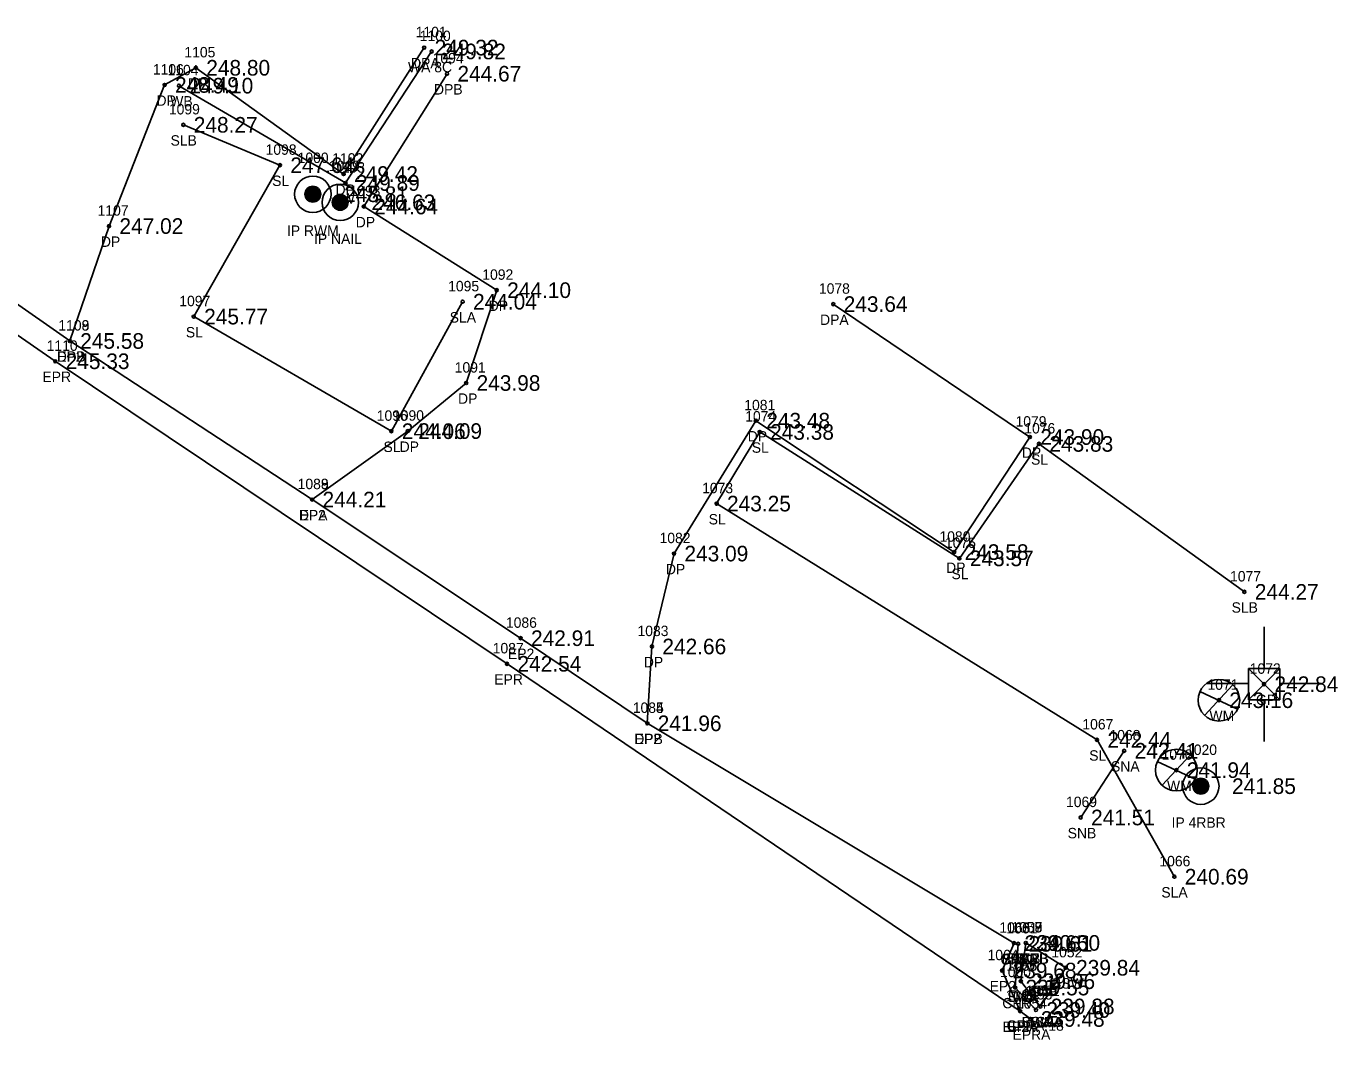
# Model space of a CAD drawing. Extents: x 1961231 to 1962574, y 799865 to 801120.
# Drawn here: x 1962180.3 to 1962306.3, y 800364.5 to 800461.9 of the extents above; entities that cross this region are included whole.
import ezdxf

# ---------------------------------------------------------------- set-up
doc = ezdxf.new("R2010")
doc.units = 0
for name, color, linetype in [('RD_EX_BldgApp', 7, 'Continuous'), ('RD_EX_BldgApp_txCode', 7, 'Continuous'), ('RD_EX_Conc', 7, 'Continuous'), ('RD_EX_Conc_txCode', 7, 'Continuous'), ('RD_EX_Driveway', 7, 'Continuous'), ('RD_EX_Driveway_txCode', 7, 'Continuous'), ('RD_EX_DV_Prop_txCode', 7, 'Continuous'), ('RD_EX_DV_PropPin', 7, 'Continuous'), ('RD_EX_Misc_txCode', 7, 'Continuous'), ('RD_EX_Road', 7, 'Continuous'), ('RD_EX_Road_txCode', 7, 'Continuous'), ('RD_EX_TX_BldgApp_ELEV', 7, 'Continuous'), ('RD_EX_TX_Conc_ELEV', 7, 'Continuous'), ('RD_EX_TX_Driveway_ELEV', 7, 'Continuous'), ('RD_EX_TX_DV_Prop_ELEV', 7, 'Continuous'), ('RD_EX_TX_Misc_ELEV', 7, 'Continuous'), ('RD_EX_TX_Road_ELEV', 7, 'Continuous'), ('RD_EX_TX_UT_ELEV', 7, 'Continuous'), ('RD_EX_TX_VEG_ELEV', 7, 'Continuous'), ('RD_EX_UT', 7, 'Continuous'), ('RD_EX_UT_txCode', 7, 'Continuous'), ('RD_EX_VEG', 7, 'Continuous'), ('RD_EX_VEG_txCode', 7, 'Continuous'), ('RD_SMD_Locator', 7, 'Continuous')]:
    doc.layers.add(name, color=color, linetype=linetype)

msp = doc.modelspace()

# ---------------------------------------------------------------- linework, layer by layer
at = {"layer": 'RD_EX_BldgApp'}
msp.add_line((1962285.75, 800392.3), (1962281.57, 800385.89), dxfattribs=at)
msp.add_lwpolyline([(1962219.21, 800459.5), (1962210.94, 800446.86), (1962194.94, 800456.21)], dxfattribs=at)
at = {"layer": 'RD_EX_Conc'}
for points in [[(1962277.69, 800367.73), (1962275.82, 800370.16), (1962276.3, 800373.84)], [(1962277.69, 800367.73), (1962280.13, 800371.45), (1962276.3, 800373.84)], [(1962277.27, 800367.4), (1962275.27, 800369.55), (1962275.56, 800373.75)]]:
    msp.add_lwpolyline(points, dxfattribs=at)
at = {"layer": 'RD_EX_Driveway'}
for points in [[(1962218.5, 800459.87), (1962210.76, 800447.72), (1962196.56, 800457.93), (1962193.56, 800456.28), (1962188.22, 800442.72), (1962184.45, 800431.68)], [(1962207.73, 800416.44), (1962216.92, 800423.02), (1962222.53, 800427.64), (1962225.47, 800436.56), (1962212.7, 800444.6), (1962220.69, 800457.36)], [(1962257.8, 800435.22), (1962276.69, 800422.45), (1962269.42, 800411.39), (1962250.36, 800424.02), (1962242.5, 800411.25), (1962240.38, 800402.32), (1962239.93, 800394.94)]]:
    msp.add_lwpolyline(points, dxfattribs=at)
at = {"layer": 'RD_EX_DV_PropPin'}
for p, q in [((1962207.07, 800445.59), (1962207.07, 800445.98)), ((1962207.1, 800445.48), (1962207.1, 800446.08)), ((1962207.14, 800445.41), (1962207.14, 800446.15)), ((1962207.17, 800445.36), (1962207.17, 800446.21)), ((1962207.21, 800445.31), (1962207.21, 800446.26)), ((1962207.24, 800445.27), (1962207.24, 800446.3)), ((1962207.28, 800445.23), (1962207.28, 800446.33)), ((1962207.31, 800445.2), (1962207.31, 800446.36)), ((1962207.35, 800445.17), (1962207.35, 800446.39)), ((1962207.38, 800445.15), (1962207.38, 800446.42)), ((1962207.42, 800445.13), (1962207.42, 800446.44)), ((1962207.45, 800445.11), (1962207.45, 800446.46)), ((1962207.49, 800445.09), (1962207.49, 800446.48)), ((1962207.52, 800445.07), (1962207.52, 800446.49)), ((1962207.56, 800445.06), (1962207.56, 800446.5)), ((1962207.59, 800445.05), (1962207.59, 800446.51)), ((1962207.63, 800445.04), (1962207.63, 800446.52)), ((1962207.66, 800445.03), (1962207.66, 800446.53)), ((1962207.7, 800445.03), (1962207.7, 800446.54)), ((1962207.73, 800445.02), (1962207.73, 800446.54)), ((1962207.77, 800445.02), (1962207.77, 800446.54)), ((1962207.8, 800445.02), (1962207.8, 800446.54)), ((1962207.84, 800445.02), (1962207.84, 800446.54)), ((1962207.87, 800445.02), (1962207.87, 800446.54)), ((1962207.91, 800445.03), (1962207.91, 800446.54)), ((1962207.94, 800445.03), (1962207.94, 800446.53)), ((1962207.98, 800445.04), (1962207.98, 800446.52)), ((1962208.01, 800445.05), (1962208.01, 800446.51)), ((1962208.05, 800445.06), (1962208.05, 800446.5)), ((1962208.08, 800445.07), (1962208.08, 800446.49)), ((1962208.12, 800445.09), (1962208.12, 800446.48)), ((1962208.15, 800445.11), (1962208.15, 800446.46)), ((1962208.19, 800445.13), (1962208.19, 800446.44)), ((1962208.22, 800445.15), (1962208.22, 800446.42)), ((1962208.26, 800445.17), (1962208.26, 800446.39)), ((1962208.29, 800445.2), (1962208.29, 800446.36)), ((1962208.33, 800445.23), (1962208.33, 800446.33)), ((1962208.36, 800445.27), (1962208.36, 800446.3)), ((1962208.4, 800445.31), (1962208.4, 800446.26)), ((1962208.43, 800445.36), (1962208.43, 800446.21)), ((1962208.47, 800445.41), (1962208.47, 800446.15)), ((1962208.5, 800445.48), (1962208.5, 800446.08)), ((1962208.54, 800445.59), (1962208.54, 800445.98)), ((1962209.98, 800444.39), (1962209.98, 800445.61)), ((1962210.01, 800444.36), (1962210.01, 800445.63)), ((1962210.05, 800444.34), (1962210.05, 800445.65)), ((1962210.08, 800444.32), (1962210.08, 800445.67)), ((1962210.12, 800444.3), (1962210.12, 800445.69)), ((1962210.15, 800444.29), (1962210.15, 800445.7)), ((1962210.19, 800444.28), (1962210.19, 800445.72)), ((1962210.22, 800444.27), (1962210.22, 800445.73)), ((1962210.26, 800444.26), (1962210.26, 800445.74)), ((1962210.29, 800444.25), (1962210.29, 800445.75)), ((1962210.33, 800444.24), (1962210.33, 800445.75)), ((1962210.36, 800444.24), (1962210.36, 800445.75)), ((1962210.4, 800444.24), (1962210.4, 800445.76)), ((1962210.43, 800444.24), (1962210.43, 800445.76)), ((1962210.47, 800444.24), (1962210.47, 800445.76)), ((1962210.5, 800444.24), (1962210.5, 800445.75)), ((1962210.54, 800444.24), (1962210.54, 800445.75)), ((1962210.57, 800444.25), (1962210.57, 800445.75)), ((1962210.61, 800444.26), (1962210.61, 800445.74)), ((1962210.64, 800444.27), (1962210.64, 800445.73)), ((1962210.68, 800444.28), (1962210.68, 800445.72)), ((1962210.71, 800444.29), (1962210.71, 800445.7)), ((1962210.75, 800444.3), (1962210.75, 800445.69)), ((1962210.78, 800444.32), (1962210.78, 800445.67)), ((1962210.82, 800444.34), (1962210.82, 800445.65)), ((1962210.85, 800444.36), (1962210.85, 800445.63)), ((1962210.89, 800444.39), (1962210.89, 800445.61)), ((1962209.7, 800444.8), (1962209.7, 800445.19)), ((1962209.73, 800444.7), (1962209.73, 800445.3)), ((1962209.77, 800444.63), (1962209.77, 800445.37)), ((1962209.8, 800444.57), (1962209.8, 800445.42)), ((1962209.84, 800444.52), (1962209.84, 800445.47)), ((1962209.87, 800444.48), (1962209.87, 800445.51)), ((1962209.91, 800444.45), (1962209.91, 800445.55)), ((1962209.94, 800444.42), (1962209.94, 800445.58)), ((1962210.92, 800444.42), (1962210.92, 800445.58)), ((1962210.96, 800444.45), (1962210.96, 800445.55)), ((1962210.99, 800444.48), (1962210.99, 800445.51)), ((1962211.03, 800444.52), (1962211.03, 800445.47)), ((1962211.06, 800444.57), (1962211.06, 800445.42)), ((1962211.1, 800444.63), (1962211.1, 800445.37)), ((1962211.13, 800444.7), (1962211.13, 800445.3)), ((1962211.17, 800444.8), (1962211.17, 800445.19)), ((1962292.38, 800388.71), (1962292.38, 800389.1)), ((1962292.41, 800388.61), (1962292.41, 800389.2)), ((1962292.45, 800388.53), (1962292.45, 800389.27)), ((1962292.48, 800388.48), (1962292.48, 800389.33)), ((1962292.52, 800388.43), (1962292.52, 800389.38)), ((1962292.55, 800388.39), (1962292.55, 800389.42)), ((1962292.59, 800388.35), (1962292.59, 800389.45)), ((1962292.62, 800388.32), (1962292.62, 800389.49)), ((1962292.66, 800388.29), (1962292.66, 800389.51)), ((1962292.69, 800388.27), (1962292.69, 800389.54)), ((1962292.73, 800388.25), (1962292.73, 800389.56)), ((1962292.76, 800388.23), (1962292.76, 800389.58)), ((1962292.8, 800388.21), (1962292.8, 800389.6)), ((1962292.83, 800388.2), (1962292.83, 800389.61)), ((1962292.87, 800388.18), (1962292.87, 800389.62)), ((1962292.9, 800388.17), (1962292.9, 800389.64)), ((1962292.94, 800388.16), (1962292.94, 800389.64)), ((1962292.97, 800388.16), (1962292.97, 800389.65)), ((1962293.01, 800388.15), (1962293.01, 800389.66)), ((1962293.04, 800388.15), (1962293.04, 800389.66)), ((1962293.08, 800388.14), (1962293.08, 800389.66)), ((1962293.11, 800388.14), (1962293.11, 800389.67)), ((1962293.15, 800388.14), (1962293.15, 800389.66)), ((1962293.18, 800388.15), (1962293.18, 800389.66)), ((1962293.22, 800388.15), (1962293.22, 800389.66)), ((1962293.25, 800388.16), (1962293.25, 800389.65)), ((1962293.29, 800388.16), (1962293.29, 800389.64)), ((1962293.32, 800388.17), (1962293.32, 800389.64)), ((1962293.36, 800388.18), (1962293.36, 800389.62)), ((1962293.39, 800388.2), (1962293.39, 800389.61)), ((1962293.43, 800388.21), (1962293.43, 800389.6)), ((1962293.46, 800388.23), (1962293.46, 800389.58)), ((1962293.5, 800388.25), (1962293.5, 800389.56)), ((1962293.53, 800388.27), (1962293.53, 800389.54)), ((1962293.57, 800388.29), (1962293.57, 800389.51)), ((1962293.6, 800388.32), (1962293.6, 800389.49)), ((1962293.64, 800388.35), (1962293.64, 800389.45)), ((1962293.67, 800388.39), (1962293.67, 800389.42)), ((1962293.71, 800388.43), (1962293.71, 800389.38)), ((1962293.74, 800388.48), (1962293.74, 800389.33)), ((1962293.78, 800388.53), (1962293.78, 800389.27)), ((1962293.81, 800388.61), (1962293.81, 800389.2)), ((1962293.85, 800388.71), (1962293.85, 800389.1))]:
    msp.add_line(p, q, dxfattribs=at)
for centre, radius in [((1962207.8, 800445.78), 1.75), ((1962207.8, 800445.78), 0.761), ((1962210.43, 800445), 1.75), ((1962210.43, 800445), 0.761), ((1962293.11, 800388.9), 1.75), ((1962293.11, 800388.9), 0.761)]:
    msp.add_circle(centre, radius, dxfattribs=at)
at = {"layer": 'RD_EX_Road'}
for points in [[(1962276.74, 800366.53), (1962275.76, 800367.28), (1962226.46, 800400.66), (1962183.05, 800429.73), (1962145.98, 800455.38), (1962104.4, 800484.06), (1962056.77, 800517.94), (1962023.95, 800541.05), (1961991.87, 800563.56), (1961983.89, 800569.94), (1961938.77, 800603.67), (1961913.43, 800623.83), (1961897.73, 800636.17), (1961851.62, 800671.61), (1961815.86, 800699.48), (1961795.77, 800715.49), (1961771.88, 800733.73), (1961750.77, 800750.96), (1961735.63, 800762.82), (1961702.92, 800788.52)], [(1962275.76, 800367.28), (1962274.03, 800371.18), (1962275.17, 800373.82), (1962239.93, 800394.94), (1962227.76, 800403.12), (1962207.73, 800416.44), (1962184.45, 800431.68), (1962152.89, 800453.77), (1962107.43, 800485.96), (1962091.52, 800497.24), (1962058.28, 800520.2), (1962027.14, 800543.26), (1961995.14, 800564.69), (1961983.89, 800569.94)]]:
    msp.add_lwpolyline(points, dxfattribs=at)
at = {"layer": 'RD_EX_UT'}
for p, q in [((1962299.19, 800400.2), (1962299.19, 800404.2)), ((1962300.69, 800400.2), (1962297.69, 800397.2)), ((1962297.69, 800400.2), (1962300.69, 800397.2)), ((1962300.69, 800400.2), (1962297.69, 800400.2)), ((1962297.69, 800400.2), (1962297.69, 800397.2)), ((1962300.69, 800397.2), (1962300.69, 800400.2)), ((1962293.02, 800398), (1962296.65, 800396.29)), ((1962293.5, 800395.71), (1962296.16, 800398.6)), ((1962297.67, 800398.75), (1962293.67, 800398.75)), ((1962300.71, 800398.77), (1962304.72, 800398.77)), ((1962297.69, 800397.2), (1962300.69, 800397.2)), ((1962299.19, 800397.2), (1962299.19, 800393.2)), ((1962289.41, 800388.99), (1962292.08, 800391.88)), ((1962288.93, 800391.28), (1962292.56, 800389.57))]:
    msp.add_line(p, q, dxfattribs=at)
for centre in [(1962294.85, 800397.16), (1962290.76, 800390.44)]:
    msp.add_circle(centre, 2, dxfattribs=at)
at = {"layer": 'RD_EX_VEG'}
for points in [[(1962222.19, 800435.45), (1962215.35, 800423.01), (1962196.36, 800434.02), (1962204.64, 800448.57), (1962195.36, 800452.45)], [(1962290.57, 800380.2), (1962283.14, 800393.35), (1962246.59, 800416.05), (1962250.73, 800422.94), (1962269.92, 800410.79), (1962277.56, 800421.79), (1962297.3, 800407.57)]]:
    msp.add_lwpolyline(points, dxfattribs=at)
at = {"layer": 'RD_SMD_Locator'}
for centre in [(1962218.5, 800459.87), (1962219.21, 800459.5), (1962196.56, 800457.93), (1962220.69, 800457.36), (1962193.56, 800456.28), (1962194.94, 800456.21), (1962195.36, 800452.45), (1962204.64, 800448.57), (1962210.76, 800447.72), (1962210.94, 800446.86), (1962207.8, 800445.78), (1962210.43, 800445), (1962212.7, 800444.6), (1962188.22, 800442.72), (1962222.19, 800435.45), (1962225.47, 800436.56), (1962257.8, 800435.22), (1962196.36, 800434.02), (1962184.45, 800431.68), (1962184.45, 800431.68), (1962183.05, 800429.73), (1962222.53, 800427.64), (1962215.35, 800423.01), (1962216.92, 800423.02), (1962250.36, 800424.02), (1962250.73, 800422.94), (1962276.69, 800422.45), (1962277.56, 800421.79), (1962207.73, 800416.44), (1962207.73, 800416.44), (1962246.59, 800416.05), (1962242.5, 800411.25), (1962269.42, 800411.39), (1962269.92, 800410.79), (1962297.3, 800407.57), (1962227.76, 800403.12), (1962240.38, 800402.32), (1962226.46, 800400.66), (1962299.19, 800398.7), (1962294.85, 800397.16), (1962239.93, 800394.94), (1962239.93, 800394.94), (1962283.14, 800393.35), (1962285.75, 800392.3), (1962290.76, 800390.44), (1962293.11, 800388.9), (1962281.57, 800385.89), (1962290.57, 800380.2), (1962275.17, 800373.82), (1962275.56, 800373.75), (1962276.3, 800373.84), (1962276.3, 800373.84), (1962276.3, 800373.84), (1962274.03, 800371.18), (1962280.13, 800371.45), (1962275.82, 800370.16), (1962275.82, 800370.16), (1962275.27, 800369.55), (1962277.27, 800367.4), (1962277.69, 800367.73), (1962277.69, 800367.73), (1962277.69, 800367.73), (1962275.76, 800367.28), (1962275.76, 800367.28), (1962276.74, 800366.53)]:
    msp.add_circle(centre, 0.15, dxfattribs=at)

# ---------------------------------------------------------------- texts
at = {"layer": 'RD_EX_BldgApp_txCode'}
for s, p in [('1068', (1962284.34, 800393.3)), ('SNA', (1962284.48, 800390.3)), ('1069', (1962280.16, 800386.89)), ('SNB', (1962280.32, 800383.89))]:
    msp.add_text(s, height=1, dxfattribs=at).set_placement(p)
at = {"layer": 'RD_EX_Conc_txCode'}
for s, p in [('1061', (1962274.43, 800374.75)), ('1057', (1962274.91, 800374.84)), ('1058', (1962274.91, 800374.84)), ('1059', (1962274.91, 800374.84)), ('CFRB', (1962273.86, 800371.75)), ('SWRB', (1962274.51, 800371.84)), ('BSWB', (1962274.51, 800371.84)), ('TCB', (1962275.03, 800371.84)), ('1052', (1962278.75, 800372.45)), ('1060', (1962273.82, 800370.55)), ('1056', (1962274.41, 800371.16)), ('1055', (1962274.44, 800371.16)), ('BSW', (1962278.82, 800369.45)), ('SWR', (1962274.51, 800368.16)), ('TC', (1962275.03, 800368.16)), ('1053', (1962275.88, 800368.4)), ('1050', (1962276.27, 800368.73)), ('1049', (1962276.3, 800368.73)), ('1051', (1962276.59, 800368.73)), ('CFR', (1962274.04, 800367.55)), ('CFRA 18', (1962274.45, 800365.4)), ('SWRA', (1962275.89, 800365.73)), ('BSWA', (1962275.89, 800365.73)), ('TCA', (1962276.41, 800365.73))]:
    msp.add_text(s, height=1, dxfattribs=at).set_placement(p)
at = {"layer": 'RD_EX_Driveway_txCode'}
for s, p in [('1101', (1962217.68, 800460.87)), ('1105', (1962195.46, 800458.93)), ('1106', (1962192.43, 800457.28)), ('DPA', (1962217.23, 800457.87)), ('1094', (1962219.31, 800458.36)), ('DP', (1962195.79, 800455.93)), ('DPB', (1962219.44, 800455.36)), ('DP', (1962192.78, 800454.28)), ('1102', (1962209.66, 800448.72)), ('DP', (1962209.98, 800445.72)), ('1093', (1962211.32, 800445.6)), ('1107', (1962187.12, 800443.72)), ('DP', (1962211.92, 800442.6)), ('DP', (1962187.44, 800440.72)), ('1092', (1962224.08, 800437.56)), ('1078', (1962256.42, 800436.22)), ('DP', (1962224.69, 800434.56)), ('1108', (1962183.35, 800432.68)), ('DPA', (1962256.53, 800433.22)), ('DPB', (1962183.2, 800429.68)), ('1091', (1962221.43, 800428.64)), ('DP', (1962221.75, 800425.64)), ('1081', (1962249.25, 800425.02)), ('1090', (1962215.5, 800424.02)), ('1079', (1962275.31, 800423.45)), ('DP', (1962249.58, 800422.02)), ('DP', (1962216.14, 800421.02)), ('DP', (1962275.91, 800420.45)), ('1088', (1962206.34, 800417.44)), ('DPA', (1962206.46, 800414.44)), ('1082', (1962241.11, 800412.25)), ('1080', (1962268, 800412.39)), ('DP', (1962268.64, 800409.39)), ('DP', (1962241.72, 800409.25)), ('1083', (1962238.99, 800403.32)), ('DP', (1962239.6, 800400.32)), ('1084', (1962238.54, 800395.94)), ('DPB', (1962238.68, 800392.94))]:
    msp.add_text(s, height=1, dxfattribs=at).set_placement(p)
at = {"layer": 'RD_EX_DV_Prop_txCode'}
for s, p in [('1000', (1962206.34, 800448.78)), ('1019', (1962209.33, 800448)), ('IP RWM', (1962205.31, 800441.78)), ('IP NAIL', (1962207.91, 800441)), ('1020', (1962291.69, 800391.9)), ('IP 4RBR', (1962290.3, 800384.9))]:
    msp.add_text(s, height=1, dxfattribs=at).set_placement(p)
at = {"layer": 'RD_EX_Misc_txCode'}
for s, p in [('1100', (1962218.07, 800460.5)), ('1104', (1962193.84, 800457.21)), ('WA 8C', (1962216.94, 800457.5)), ('WB', (1962194.1, 800454.21)), ('1103', (1962209.84, 800447.86)), ('W', (1962210.57, 800444.86))]:
    msp.add_text(s, height=1, dxfattribs=at).set_placement(p)
at = {"layer": 'RD_EX_Road_txCode'}
for s, p in [('1109', (1962183.35, 800432.68)), ('1110', (1962182.23, 800430.73)), ('EP2', (1962183.24, 800429.68)), ('EPR', (1962181.82, 800427.73)), ('1089', (1962206.34, 800417.44)), ('EP2', (1962206.52, 800414.44)), ('1086', (1962226.35, 800404.12)), ('1087', (1962225.08, 800401.66)), ('EP2', (1962226.55, 800401.12)), ('EPR', (1962225.23, 800398.66)), ('1085', (1962238.54, 800395.94)), ('EP2', (1962238.72, 800392.94)), ('1065', (1962273.76, 800374.82)), ('1064', (1962272.62, 800372.18)), ('EP2', (1962273.96, 800371.82)), ('EP2', (1962272.83, 800369.18)), ('1062', (1962274.35, 800368.28)), ('1063', (1962274.35, 800368.28)), ('1054', (1962275.35, 800367.53)), ('EP2A', (1962274.07, 800365.28)), ('EPR', (1962274.53, 800365.28)), ('EPRA', (1962275.02, 800364.53))]:
    msp.add_text(s, height=1, dxfattribs=at).set_placement(p)
at = {"layer": 'RD_EX_TX_BldgApp_ELEV'}
for s, p in [('242.41', (1962286.75, 800391.55)), ('241.51', (1962282.57, 800385.14))]:
    msp.add_text(s, height=1.5, dxfattribs=at).set_placement(p)
at = {"layer": 'RD_EX_TX_Conc_ELEV'}
for s, p in [('239.61', (1962276.56, 800373)), ('240.00', (1962277.3, 800373.09)), ('240.00', (1962277.3, 800373.09)), ('240.00', (1962277.3, 800373.09)), ('239.84', (1962281.13, 800370.7)), ('239.55', (1962276.27, 800368.8)), ('239.96', (1962276.82, 800369.41)), ('239.96', (1962276.82, 800369.41)), ('239.40', (1962278.27, 800366.65)), ('239.88', (1962278.69, 800366.98)), ('239.88', (1962278.69, 800366.98)), ('239.88', (1962278.69, 800366.98))]:
    msp.add_text(s, height=1.5, dxfattribs=at).set_placement(p)
at = {"layer": 'RD_EX_TX_Driveway_ELEV'}
for s, p in [('249.32', (1962219.5, 800459.12)), ('248.80', (1962197.56, 800457.18)), ('248.49', (1962194.56, 800455.53)), ('244.67', (1962221.69, 800456.61)), ('249.42', (1962211.76, 800446.97)), ('244.64', (1962213.7, 800443.85)), ('247.02', (1962189.22, 800441.97)), ('244.10', (1962226.47, 800435.81)), ('243.64', (1962258.8, 800434.47)), ('245.58', (1962185.45, 800430.93)), ('243.98', (1962223.53, 800426.89)), ('243.48', (1962251.36, 800423.27)), ('244.09', (1962217.92, 800422.27)), ('243.90', (1962277.69, 800421.7)), ('244.21', (1962208.73, 800415.69)), ('243.09', (1962243.5, 800410.5)), ('243.58', (1962270.42, 800410.64)), ('242.66', (1962241.38, 800401.57)), ('241.96', (1962240.93, 800394.19))]:
    msp.add_text(s, height=1.5, dxfattribs=at).set_placement(p)
at = {"layer": 'RD_EX_TX_DV_Prop_ELEV'}
for s, p in [('248.81', (1962210.8, 800445.03)), ('246.63', (1962213.43, 800444.25)), ('241.85', (1962296.11, 800388.15))]:
    msp.add_text(s, height=1.5, dxfattribs=at).set_placement(p)
at = {"layer": 'RD_EX_TX_Misc_ELEV'}
for s, p in [('249.82', (1962220.21, 800458.75)), ('249.10', (1962195.94, 800455.46)), ('249.89', (1962211.94, 800446.11))]:
    msp.add_text(s, height=1.5, dxfattribs=at).set_placement(p)
at = {"layer": 'RD_EX_TX_Road_ELEV'}
for s, p in [('245.58', (1962185.45, 800430.93)), ('245.33', (1962184.05, 800428.98)), ('244.21', (1962208.73, 800415.69)), ('242.91', (1962228.76, 800402.37)), ('242.54', (1962227.46, 800399.91)), ('241.96', (1962240.93, 800394.19)), ('239.65', (1962276.17, 800373.07)), ('239.68', (1962275.03, 800370.43)), ('239.53', (1962276.76, 800366.53)), ('239.53', (1962276.76, 800366.53)), ('239.48', (1962277.74, 800365.78))]:
    msp.add_text(s, height=1.5, dxfattribs=at).set_placement(p)
at = {"layer": 'RD_EX_TX_UT_ELEV'}
for s, p in [('242.84', (1962300.19, 800397.95)), ('243.16', (1962295.85, 800396.41)), ('241.94', (1962291.76, 800389.69))]:
    msp.add_text(s, height=1.5, dxfattribs=at).set_placement(p)
at = {"layer": 'RD_EX_TX_VEG_ELEV'}
for s, p in [('248.27', (1962196.36, 800451.7)), ('247.64', (1962205.64, 800447.82)), ('244.04', (1962223.19, 800434.7)), ('245.77', (1962197.36, 800433.27)), ('244.06', (1962216.35, 800422.26)), ('243.38', (1962251.73, 800422.19)), ('243.83', (1962278.56, 800421.04)), ('243.25', (1962247.59, 800415.3)), ('243.57', (1962270.92, 800410.04)), ('244.27', (1962298.3, 800406.82)), ('242.44', (1962284.14, 800392.6)), ('240.69', (1962291.57, 800379.45))]:
    msp.add_text(s, height=1.5, dxfattribs=at).set_placement(p)
at = {"layer": 'RD_EX_UT_txCode'}
for s, p in [('1072', (1962297.81, 800399.7)), ('1071', (1962293.75, 800398.16)), ('GP', (1962298.41, 800396.7)), ('WM', (1962293.94, 800395.16)), ('1070', (1962289.34, 800391.44)), ('WM', (1962289.86, 800388.44))]:
    msp.add_text(s, height=1, dxfattribs=at).set_placement(p)
at = {"layer": 'RD_EX_VEG_txCode'}
for s, p in [('1099', (1962193.97, 800453.45)), ('SLB', (1962194.13, 800450.45)), ('1098', (1962203.26, 800449.57)), ('SL', (1962203.89, 800446.57)), ('1095', (1962220.8, 800436.45)), ('1097', (1962194.97, 800435.02)), ('SLA', (1962220.95, 800433.45)), ('SL', (1962195.6, 800432.02)), ('1096', (1962213.94, 800424.01)), ('1074', (1962249.34, 800423.94)), ('1076', (1962276.15, 800422.79)), ('SL', (1962214.59, 800421.01)), ('SL', (1962249.97, 800420.94)), ('SL', (1962276.8, 800419.79)), ('1073', (1962245.2, 800417.05)), ('SL', (1962245.83, 800414.05)), ('1075', (1962268.53, 800411.79)), ('SL', (1962269.16, 800408.79)), ('1077', (1962295.92, 800408.57)), ('SLB', (1962296.07, 800405.57)), ('1067', (1962281.73, 800394.35)), ('SL', (1962282.39, 800391.35)), ('1066', (1962289.13, 800381.2)), ('SLA', (1962289.32, 800378.2))]:
    msp.add_text(s, height=1, dxfattribs=at).set_placement(p)

doc.saveas('drawing.dxf')
